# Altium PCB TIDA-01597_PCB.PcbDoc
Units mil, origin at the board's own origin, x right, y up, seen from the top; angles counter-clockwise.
Board outline 1013 x 1011.96 mil, 2 copper layers (Top Layer, Bottom Layer), stack 62 mil thick; 20 components, 17 nets, 61 pads, 15 vias.
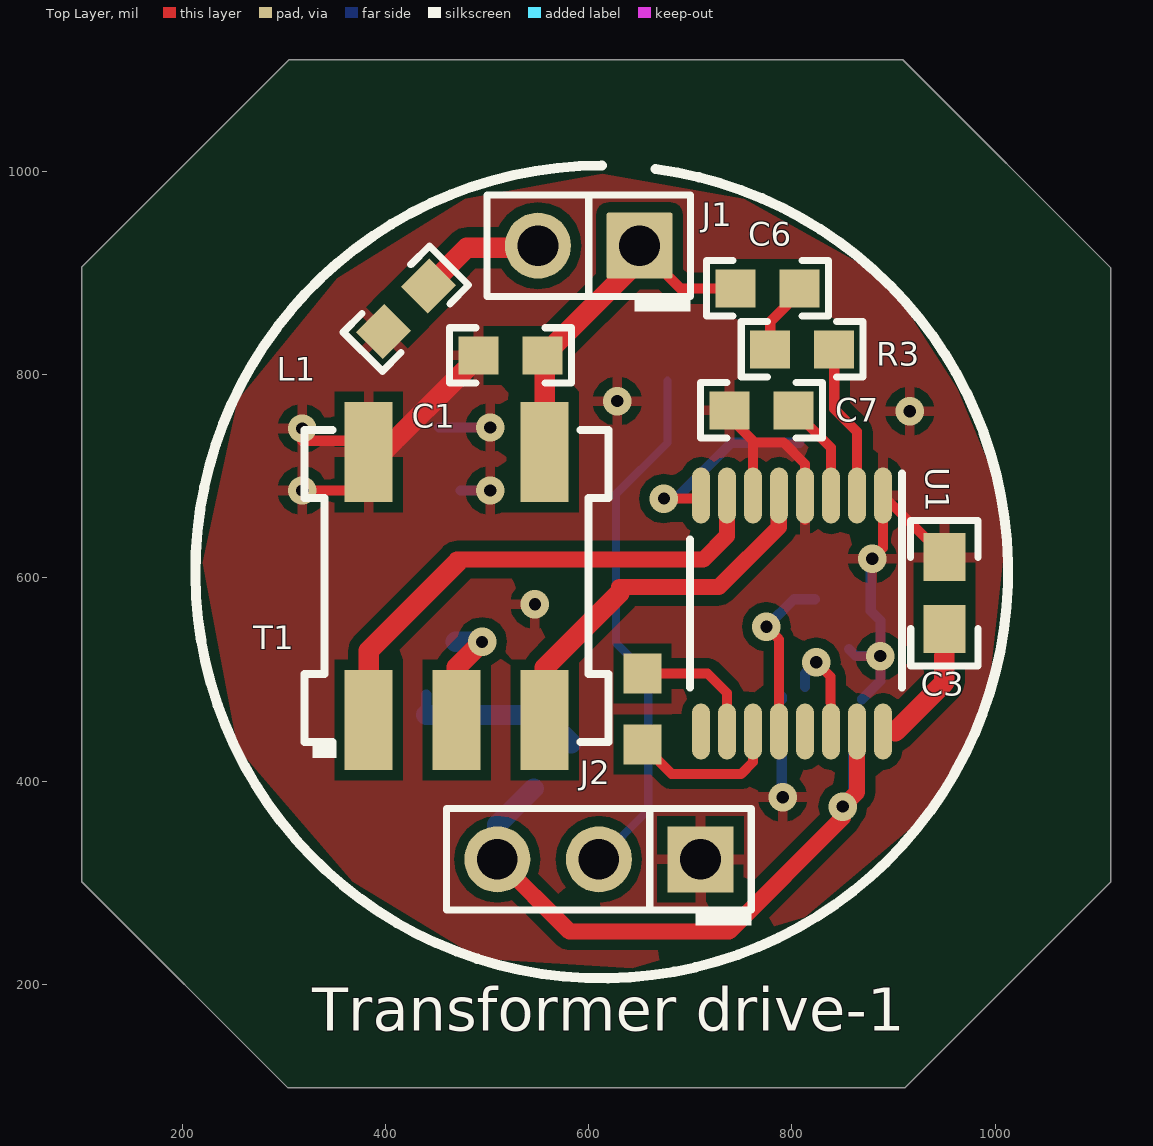
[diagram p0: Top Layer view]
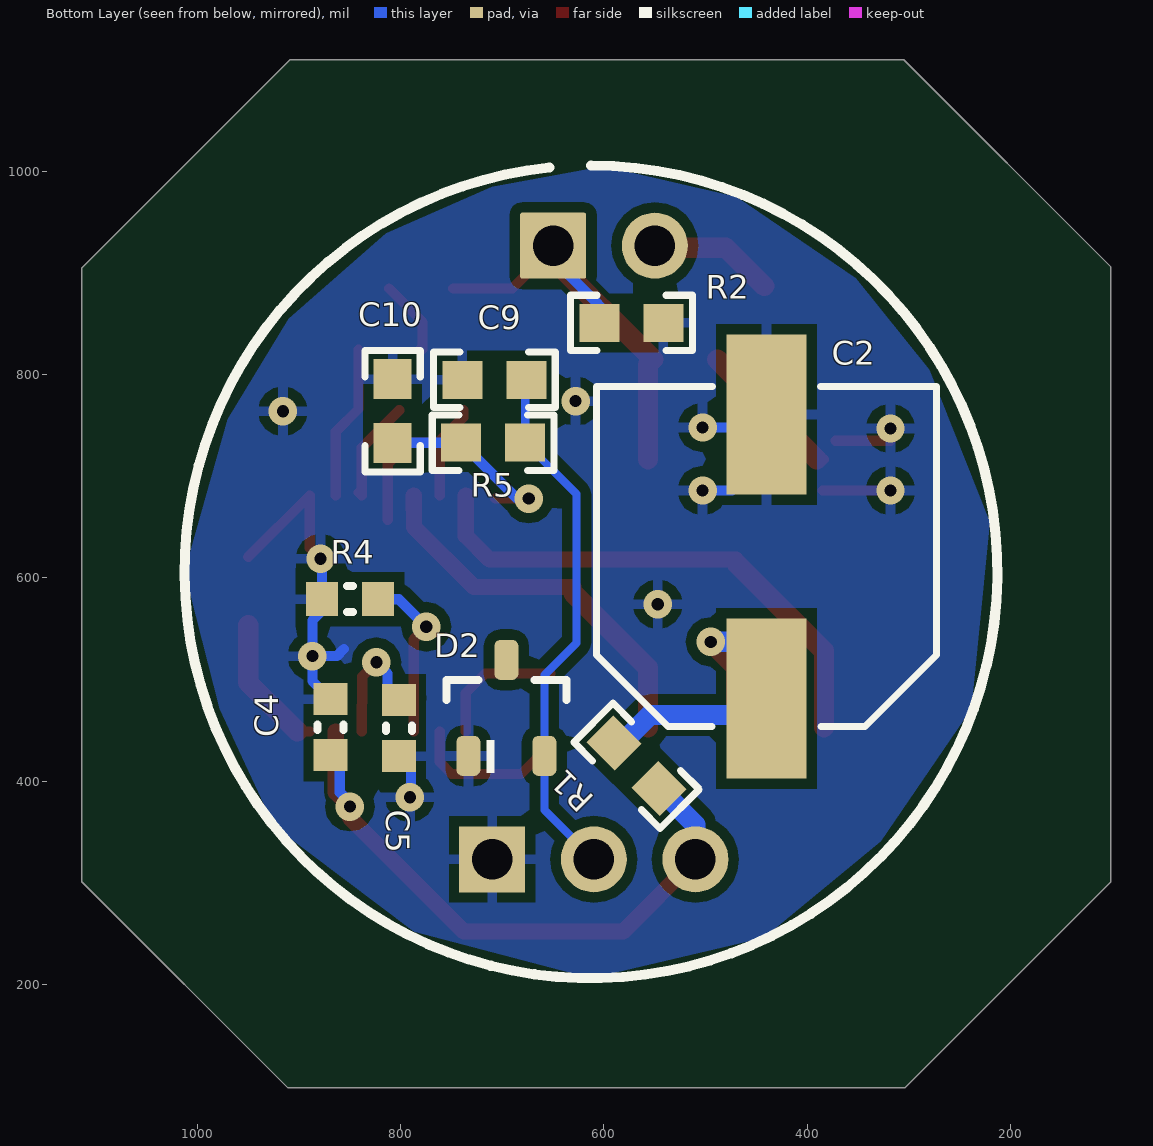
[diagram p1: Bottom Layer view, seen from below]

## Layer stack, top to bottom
Top Solder: solder mask 0.4, Solder Resist, Dk 3.5
Top Layer: signal copper 1.4
Dielectric1: core 59.2, FR-4, Dk 4.8
Bottom Layer: signal copper 1.4
Bottom Solder: solder mask 0.4, Solder Resist, Dk 3.5

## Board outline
304.95,1109.95 909.05,1109.95 1114,905 1114,301 911,98 304,98 101,301 101,906

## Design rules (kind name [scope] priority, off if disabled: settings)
AcuteAngle [All] p1: minimum=4.50000000000000E+0001 checktracksonly=FALSE
AssemblyTestPointUsage [All] p1: valid=2
BoardOutlineClearance BoardOutlineClearance_MountingHoles [OnCopper and InComponentClass('Mounting Holes')] p1: gap=40 ignorepadtopadclearanceinfootprint=FALSE
BoardOutlineClearance BoardOutlineClearance_Poly [OnCopper and IsPoly] p2: gap=25 ignorepadtopadclearanceinfootprint=FALSE
BoardOutlineClearance [OnCopper and Not InComponentClass('Logo') and not InComponentClass('FiducialMark') and not InRegion(1000,500,4000,800) and not InPoly] p3: gap=75 ignorepadtopadclearanceinfootprint=FALSE
Clearance Clearance_Keepouts [((IsTrack Or IsArc) And Not InPoly) And IsFree and IsKeepOut vs ((IsTrack Or IsArc) And Not InPoly) And IsFree and IsKeepOut] p1: gap=0 ignorepadtopadclearanceinfootprint=FALSE
Clearance Clearance_Poly [InPolygon] p2: gap=10 ignorepadtopadclearanceinfootprint=FALSE except(0: Arc-Hole Track-Hole SMDPad-Hole THPad-Hole Via-Hole Fill-Hole Poly-Hole Region-Hole Text-Hole)
Clearance [All] p3: gap=7.87 ignorepadtopadclearanceinfootprint=FALSE except(0: Arc-Hole Track-Hole SMDPad-Hole THPad-Hole Via-Hole Fill-Hole Poly-Hole Region-Hole Text-Hole)
ComponentClearance ComponentClearance_MountingHoles_FiducialMarks [InComponentClass('Mounting Holes') vs InComponentClass('FiducialMark')] p1: gap=50 collisioncheckmode=3 verticalgap=10 showdistances=FALSE
ComponentClearance ComponentClearance_Shunt [InComponentClass('Header') vs InComponentClass('Shunt')] p2: gap=0 collisioncheckmode=3 verticalgap=0 showdistances=FALSE
ComponentClearance ComponentClearance_Logo [InComponentClass('Logo')] p3: gap=50 collisioncheckmode=3 verticalgap=10 showdistances=FALSE
ComponentClearance ComponentClearance_ScrewToNut [(HasFootprint('NY PMS 440 0025 PH')) vs (HasFootprint('Keystone_1902C'))] p4: gap=5 collisioncheckmode=3 verticalgap=10 showdistances=FALSE
ComponentClearance ComponentClearance_MountingHoles [InComponentClass('Mounting Holes')] p5: gap=250 collisioncheckmode=3 verticalgap=100000 showdistances=FALSE
ComponentClearance ComponentClearance_SmallPassives [HasFootprint('0201*') or HasFootprint('0402*') or HasFootprint('0508') or HasFootprint('0603*') or HasFootprint('0612') or HasFootprint('0805*') or HasFootprint('0815*') or HasFootprint('0830*') or HasFootprint('1206*') or HasFootprint('1210*') or HasFootprint('1808*') or HasFootprint('1812*') or HasFootprint('1825*') or HasFootprint('2010*') or HasFootprint('2220*') or HasFootprint('2225*') or HasFootprint('2512*') or HasFootprint('2728*') or HasFootprint('3518*') vs HasFootprint('0201*') or HasFootprint('0402*') or HasFootprint('0508') or HasFootprint('0603*') or HasFootprint('0612') or HasFootprint('0805*') or HasFootprint('0815*') or HasFootprint('0830*') or HasFootprint('1206*') or HasFootprint('1210*') or HasFootprint('1808*') or HasFootprint('1812*') or HasFootprint('1825*') or HasFootprint('2010*') or HasFootprint('2220*') or HasFootprint('2225*') or HasFootprint('2512*') or HasFootprint('2728*') or HasFootprint('3518*')] p6: gap=6 collisioncheckmode=3 verticalgap=10 showdistances=FALSE
ComponentClearance ComponentClearance_THtoSMT [IsThruComponent vs IsSMTComponent] p7: gap=35 collisioncheckmode=3 verticalgap=30 showdistances=FALSE
ComponentClearance ComponentClearance_THtoTH [IsThruComponent vs IsThruComponent] p8: gap=30 collisioncheckmode=3 verticalgap=30 showdistances=FALSE
ComponentClearance [All] p9: gap=30 collisioncheckmode=3 verticalgap=10 showdistances=FALSE
DiffPairsRouting [All] p1: maxlimit=100 minlimit=10 mostfreqgap=10 toplayer_minwidth=15 toplayer_maxwidth=15 toplayer_prefwidth=15 bottomlayer_minwidth=15 bottomlayer_maxwidth=15 bottomlayer_prefwidth=15 maxuncoupledlength=1000
FabricationTestPointUsage TestPointUsage [All] p1: valid=2 allowmultiple=FALSE
FabricationTestpoint Testpoint [All] p1: side=3 testpointundercomponent=TRUE minsize=40 maxsize=100 preferedsize=60 minholesize=0 maxholesize=40 preferedholesize=32 testpointgrid=1 allowsidetop=TRUE allowsidebottom=TRUE usegrid=TRUE gridtolerance=0.01
FanoutControl Fanout_LCC [IsLCC] p1: bgadir=Out bgaviamode=Centered fanoutstyle=Auto fanoutdirection=Alternating viagrid=1 // Fanout_LCC (Default Rule)
FanoutControl Fanout_BGA [IsBGA] p2: bgadir=Out bgaviamode=Centered fanoutstyle=Auto fanoutdirection=Alternating viagrid=1 // Fanout_BGA (Default Rule)
FanoutControl Fanout_Default [All] p4: bgadir=Out bgaviamode=Centered fanoutstyle=Auto fanoutdirection=Alternating viagrid=1 // Fanout_Default (Default Rule)
FanoutControl Fanout_Small [(CompPinCount < 5)] p5: bgadir=Out bgaviamode=Centered fanoutstyle=Auto fanoutdirection=OutThenIn viagrid=1 // Fanout_Small (Default Rule)
HoleSize [All] p1: absolutevalues=TRUE maxlimit=251 minlimit=7.87 maxpercent=80.000 minpercent=20.000
MinimumAnnularRing MinimumAnnularRing_ThermalPadVias [IsVia and InAnyComponent] p1: minimumring=5.91
MinimumAnnularRing [All] p2: minimumring=8
MinimumSolderMaskSliver MinimumSolderMaskSliver_Logo [InComponentClass('Logo') vs InComponentClass('Logo')] p1: minsoldermaskwidth=0.7
MinimumSolderMaskSliver [All] p2: minsoldermaskwidth=3.94
PlaneConnect [All] p1: planeconnectstyle=Relief reliefexpansion=10 reliefentries=4 reliefconductorwidth=10 reliefairgap=10
PolygonConnect [All] p1: connectstyle=Relief reliefconductorwidth=10 reliefentries=4 polygonreliefangle="90 Angle" airgapwidth=10
RoutingVias ThermalPadVias [IsVia and InAnyComponent] p1: holewidth=7.87 width=19.68 viastyle="Through Hole" minholewidth=7.87 minwidth=19.68 maxholewidth=12.99 maxwidth=23.62
RoutingVias [All] p2 off: holewidth=16 width=34 viastyle="Through Hole" minholewidth=7.87 minwidth=26 maxholewidth=40 maxwidth=65
SilkToBoardRegionClearance [Not ((IsComment or IsDesignator) And (Hide <> 'False')) and not InRegion(1000,500,4000,800)] p1:
SilkToSilkClearance SilkToSilkClearance_Pb-FreeLogo [(HasFootprint('Pb-Free_Overlay_Medium') OR HasFootprint('Pb-Free_Overlay_Small')) vs (HasFootprint('Pb-Free_Overlay_Medium') OR HasFootprint('Pb-Free_Overlay_Small'))] p1: silktosilkclearance=0
SilkToSilkClearance [All] p2: silktosilkclearance=4
SilkToSolderMaskClearance SilkToComponentPadClearance [(IsPad or IsFill or IsRegion) and InAnycomponent] p1 off: minsilkscreentomaskgap=5 clearancetoexposedcopper=TRUE
SilkToSolderMaskClearance "Silk to Solder Mask Opening" [All] p2 off: minsilkscreentomaskgap=4 clearancetoexposedcopper=FALSE
SolderMaskExpansion [All] p1: expansion=1.97
Width [All] p1: maxlimit=100 minlimit=6 preferedwidth=10 checkconnectedcopper=TRUE
15 further rules are at their usual default settings.

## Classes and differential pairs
component class Header: J1 J2 J9 J10

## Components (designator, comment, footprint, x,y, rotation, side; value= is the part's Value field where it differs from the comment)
C1 "GRM188R72A152KA01D" 0603 523,819 r180 top value=1500pF
C2 "EEE-FK1V101P" SM_RADIAL_F 440,621 r90 bottom value=100uF
C3 "C1608X7R1E104K080AA" 0603M 950.08,584.94 r90 top value=0.1uF
C4 "C1608X7R1E104K080AA" 0603L 869,453 r90 bottom value=0.1uF
C5 "C1608X7R1E104K080AA" 0603L 802,452 r270 bottom value=0.1uF
C6 "GRM1885C2A391JA01D" 0603 776,885 r180 top value=390pF
C7 "06035C333JAT2A" 0603 770.08,764.94 r180 top value=0.033uF
C9 "GRM1885C1H181JA01D" 0603 708,795 r0 bottom value=180pF
C10 "GRM1885C1H181JA01D" 0603 808,764 r90 bottom value=180pF
D2 "MMBZ27VCL-7-F" SOT-23 696,472 r90 bottom value=27V
J1 "TSW-102-07-G-S" TSW-102-07-G-S 600,927 r180 top
J2 "TSW-103-07-G-S" TSW-103-07-G-S 610,323 r180 top
L1 "74279264" 0603 420.08,864.94 r45 top value="300 ohm"
R1 "CRCW0603100RJNEA" 0603 568,415 r225 bottom value=100
R2 "RC0603JR-072K7L" 0603 573,851 r0 bottom value=2.7k
R3 "CRCW0603100RJNEA" 0603 810.08,824.94 r0 top value=100
R4 "RC0603JR-0710KL" 0603L 850,579 r180 bottom value=10k
R5 "CRCW0603100RFKEA" 0603 709,733 r0 bottom value=100
T1 "B78416A2232A003" TDK_B78416A2232A003 470,592 r90 top value=3mH
U1 "PGA460TPWRQ1" PW0016A_N 800.08,564.94 r270 top

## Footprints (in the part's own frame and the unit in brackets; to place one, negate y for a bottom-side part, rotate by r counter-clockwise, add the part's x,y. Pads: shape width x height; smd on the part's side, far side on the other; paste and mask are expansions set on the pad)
0603 [mm] "0603 from SM-752 data"
  rect 1x0.95 smd: 1(-0.8,0) 2(0.8,0)
  silkscreen extent -1.52,-0.69 1.52,0.69, body extent -0.87,-0.47 0.87,0.47, height 1
0603L [mm] "0603 from SM-752 data"
  rect 0.8x0.85 smd: 1(-0.7,0) 2(0.7,0)
  silkscreen extent -0.07,-0.33 0.07,0.33, body extent -0.87,-0.47 0.87,0.47, height 1
0603M [mm] "0603 from SM-752 data"
  rect 1.2x1.05 smd: 1(-0.9,0) 2(0.9,0)
  silkscreen extent -1.82,-0.84 1.82,0.84, body extent -0.87,-0.47 0.87,0.47, height 1
PW0016A_N [mm] "TSOP, 16-Leads, Body 5x4.4mm, Pitch 0.65mm, IPC Medium Density"
  oval 1.4x0.45 smd: 1(-2.95,2.275) 2(-2.95,1.625) 3(-2.95,0.975) 4(-2.95,0.325) 5(-2.95,-0.325) 6(-2.95,-0.975) 7(-2.95,-1.625) 8(-2.95,-2.275) 9(2.95,-2.275) 10(2.95,-1.625) 11(2.95,-0.975) 12(2.95,-0.325) 13(2.95,0.325) 14(2.95,0.975) 15(2.95,1.625) 16(2.95,2.275)
  silkscreen extent -3.5,-2.55 1.85,2.75, body extent -3.21,-2.5 3.21,2.5, height 1
SM_RADIAL_F [mm] "8 x 10.2mm:  Panasonic F"
  rect 4x2 smd: 1(-3.55,0) 2(3.55,0)
  silkscreen extent -4.25,-4.25 4.25,4.25, body extent -4.25,-4.25 4.25,4.25, height 10.5
SOT-23 [mm] "SOT23, 3-Leads, Body 2.9x1.3mm, Pitch 0.95mm, Lead Span 2.5mm, IPC Medium Density"
  rrect50% 1x0.6 smd: 1(-1.2,0.95) 2(-1.2,-0.95) 3(1.2,0)
  silkscreen extent -1.62,-1.5 0.7,1.5, body extent -1.16,-1.45 1.21,1.45, height 1
TDK_B78416A2232A003 [mm] "SMT, 5-Leads, Body 8.8x7.6mm"
  rect 2.5x1.2 smd: 1(-3.35,2.2) 2(-3.35,0) 3(-3.35,-2.2) 4(3.35,-2.2) 6(3.35,2.2)
  silkscreen extent -4.3,-3.8 3.9,3.8, body extent -4.5,-3.8 4.5,3.8, height 7.1
TSW-102-07-G-S [mm] "Samtec 100mil, 1x2, 230 mil above insulator"
  rrect6% 1.65x1.65 hole 1.016: 1(-1.27,0)
  round 1.65 hole 1.016: 2(1.27,0)
  silkscreen extent -2.54,-1.27 2.54,1.65, body extent -2.54,-1.27 2.54,1.27, height 8.38
TSW-103-07-G-S [mm] "Samtec 100mil, 1x3, 230 mil above insulator"
  rect 1.65x1.65 hole 1.016: 1(-2.54,0)
  round 1.65 hole 1.016: 2(0,0) 3(2.54,0)
  silkscreen extent -3.81,-1.27 3.81,1.65, body extent -3.81,-1.27 3.81,1.27, height 8.38

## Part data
C1: "CAP, CERM, 1500 pF, 100 V, +/- 10%, X7R, 0603", Cap_Case=0603, Manufacturer=MuRata, Supplier Part Number 1=490-1475-1-ND, TempCo=X7R, Tolerance_%=10, Value1=Unknown, Value2=100V, ValueDisplayed=1500pF
C2: "CAP, AL, 100 µF, 35 V, +/- 20%, 0.16 ohm, AEC-Q200 Grade 2, SMD", Cap_Case=F, Manufacturer=Panasonic, Supplier Part Number 1=PCE3835CT-ND, Tolerance_%=20, Value1="0.16 ohm", Value2=35V, ValueDisplayed=100µF
C3 C4 C5: "CAP, CERM, 0.1 µF, 25 V, +/- 10%, X7R, 0603", Cap_Case=0603, Manufacturer=TDK, Supplier Part Number 1=445-1316-1-ND, TempCo=X7R, Tolerance_%=10, Value1=Unknown, Value2=25V, ValueDisplayed=0.1µF
C6: "CAP, CERM, 390 pF, 100 V, +/- 5%, C0G/NP0, 0603", Cap_Case=0603, Manufacturer=MuRata, Supplier Part Number 1=490-1365-1-ND, TempCo=C0G/NP0, Tolerance_%=5, Value1=Unknown, Value2=100V, ValueDisplayed=390pF
C7: "CAP, CERM, 0.033 µF, 50 V, +/- 5%, X7R, 0603", Cap_Case=0603, Manufacturer=AVX, Supplier Part Number 1=478-3723-1-ND, TempCo=X7R, Tolerance_%=5, Value1=Unknown, Value2=50V, ValueDisplayed=0.033µF
C9 C10: "CAP, CERM, 180 pF, 50 V,+/- 5%, C0G/NP0, 0603", Cap_Case=0603, Manufacturer=MuRata, Supplier Part Number 1=490-1433-1-ND, TempCo=C0G/NP0, Tolerance_%=5, Value2=50V, ValueDisplayed=180pF
D2: "Diode, TVS, Uni, 27 V, 38 Vc, SOT-23", Manufacturer="Diodes Inc.", Power_W=0.225, Supplier Part Number 1=MMBZ27VCL-FDICT-ND, Value1=0.225W
J1: "Header, 100mil, 2x1, Gold, TH", Color=Black, Current_A=6.3, Manufacturer=Samtec, Supplier Part Number 1=SAM1029-02-ND, Voltage_V=550
J2: "Header, 100mil, 3x1, Gold, TH", Color=Black, Current_A=6.3, Manufacturer=Samtec, Supplier Part Number 1=SAM1029-03-ND, Voltage_V=550
L1: "Ferrite Bead, 300 ohm @ 100 MHz, 0.2 A, 0603", Manufacturer="Wurth Elektronik", Supplier Part Number 1=732-4630-1-ND, Value1="0.35 ohm", Value2=0.2A, ValueDisplayed="300 ohm"
R1 R3: "RES, 100, 5%, 0.1 W, 0603", Manufacturer=Vishay-Dale, Power_W=0.1, Supplier Part Number 1=541-100GCT-ND, TempCo="200 ppm/C", Tolerance_%=5, Value1=5%, Value2=0.1W, Value_Code=100R, ValueDisplayed=100
R2: "RES, 2.7 k, 5%, 0.1 W, 0603", Manufacturer="Yageo America", Power_W=0.1, Supplier Part Number 1=311-2.7KGRCT-ND, TempCo="100 ppm/C", Tolerance_%=5, Value1=5%, Value2=0.1W, Value_Code=2k70, ValueDisplayed=2.7k
R4: "RES, 10 k, 5%, 0.1 W, 0603", Manufacturer="Yageo America", Power_W=0.1, Supplier Part Number 1=311-10KGRCT-ND, TempCo="100 ppm/C", Tolerance_%=5, Value1=5%, Value2=0.1W, Value_Code=10k0, ValueDisplayed=10k
R5: "RES, 100, 1%, 0.1 W, 0603", Manufacturer=Vishay-Dale, Power_W=0.1, Supplier Part Number 1=541-100HCT-ND, TempCo="100 ppm/C", Tolerance_%=1, Value1=1%, Value2=0.1W, Value_Code=100R, ValueDisplayed=100
T1: "Transformer, 3 mH, SMT", Manufacturer=TDK, Supplier Part Number 1=495-6812-1-ND, ValueDisplayed=3mH
U1: "PGA460TPWRQ1, PW0016A (TSSOP-16)", Alternate Manufacturer="Texas Instruments"

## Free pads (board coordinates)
  rect 37.4x39.37 smd: 105(652.78,505.91) 106(652.78,435.91)

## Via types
v1: diameter 28, hole 12, Top Layer to Bottom Layer, 15 vias

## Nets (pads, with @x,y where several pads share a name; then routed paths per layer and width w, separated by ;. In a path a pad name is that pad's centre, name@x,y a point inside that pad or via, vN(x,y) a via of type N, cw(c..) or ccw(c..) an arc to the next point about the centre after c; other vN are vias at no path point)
GND: C1.2 C2.2 C3.2 C4.2 C5.2 C7.2 C9.2 C10.2 D2.1 J2.1 L1.1 R2.1 R4.1 T1.6 U1.1 U1.4 U1.6 | length 926
  Top Layer w10: v1(318,686) T1.6@385,686 ; v1@318,735 T1.6@372.28,735 ; T1.6@383.46,716.83 T1.6@390.47,716.83 ; C7.2 738.58,758.05 761.69,734.94 ; U1.6 761.69,734.94 ; U1.4@812.87,657.14 U1.4 812.87,712.14 791.65,733.37 763.27,733.37 761.69,734.94 ; v1(879,618.86) 889.65,629.51 U1.1 C3.2@950.08,620.65
  Top Layer w20: T1.6@390.47,716.83 C1.2@488.58,814.94
  Bottom Layer w10: C2.2@452.76,748 v1@501,748 ; C2.2@474,686 v1@501,686 ; v1@790,385 C5.2@790,425.44 ; 856,530 863,523 v1(887,523) ; C4.2 887,498.56 v1(887,523) ; v1@877.56,617.42 R4.1 877.56,567.44 887,558 v1(887,523)
  other v1: 791,384 547,574 503,686 318,747 503,748 916,764 628,774
NetC1_1: C1.1 C6.2 J1.1 R2.2 T1.4 | length 473.7
  Top Layer w10: C1.1@551.57,814.94 C1.1@556.69,809.82 ; J1.1@650.08,924.94 690.08,884.94 C6.2@748.58,884.94
  Top Layer w20: C1.1@551.57,814.94 J1.1@654,917 ; T1.4@556.69,716.83 C1.1@556.69,809.82
  Bottom Layer w10: R2.2@590.39,853.64 J1.1@652,916 ; J1.1@651.57,906.44 J1.1@670.08,924.94
NetC2_1: C2.1 R1.1 T1.2 | length 290.6
  Top Layer w20: T1.2 470,512 v1(495,537)
  Bottom Layer w10: C2.1@440.08,465.18 C2.1@440.08,484.94 ; v1@496,538 v1@497,537
  Bottom Layer w20: C2.1@440.08,465.18 555,465 R1.1@582.73,437.27 ; C2.1@469,537 v1(495,537) v1@497,537
NetC3_1: C3.1 U1.16 | length 136.7
  Top Layer w10: U1.16 901.8,448.8
  Top Layer w20: 901.8,449 902,449 950,497 C3.1@950.08,553.44
NetC5_1: C5.1 U1.14 | length 105.4
  Top Layer w10: v1(824,517) 838,503 U1.14
  Bottom Layer w10: C5.1@790,480.56 C5.1@790,483 ; C5.1@813,492.56 813,506 v1(824,517)
NetC6_1: C6.1 R3.1 | length 76.7
  Top Layer w10: R3.1@781.57,824.94 R3.1 778.58,851.95 C6.1@811.57,884.94
NetC7_1: C7.1 U1.3 | length 103.5
  Top Layer w10: C7.1 838.46,728.05 U1.3 U1.3@841.57,684.19
NetC9_1: C9.1 D2.2 J2.2 R5.1 | length 525.1
  Bottom Layer w8: J2.2 658.6,371.6 658.6,489.76 658.6,504.4 627,536 627,682.5 R5.1 C9.1@677.5,794
NetC10_1: C10.1 R5.2 U1.8 | length 189.7
  Top Layer w10: v1(674,678) U1.8@707.43,678
  Bottom Layer w10: v1(674,678) 685.5,678 R5.2 C10.1@807.5,733
NetJ1_2: J1.2 L1.2 | length 123.4
  Top Layer w20: L1.2 480.08,924.94 J1.2@550.08,924.94
NetR3_2: R3.2 U1.2 | length 153.2
  Top Layer w10: R3.2 841.57,766.27 864.06,743.79 U1.2
NetR4_2: R4.2 U1.12 | length 167
  Top Layer w10: v1(774.86,551.86) 787.28,539.44 U1.12
  Bottom Layer w10: v1(774.86,551.86) 802,579 R4.2
NetT1_1: T1.1 U1.7 | length 513.2
  Top Layer w16: 470,618 712.73,618 736.02,641.29 U1.7
  Top Layer w20: T1.1@383.46,453.05 383.46,528.33 470.08,614.94
NetT1_3: T1.3 U1.5 | length 374.8
  Top Layer w16: 630,591 728,591 787,650 U1.5
  Top Layer w20: T1.3@556.69,453.05 556.69,511.55 630.08,584.94
RXD: pad.106 U1.11 | length 155.8
  Top Layer w10: pad.106 681.68,407 750,407 761.69,418.69 U1.11
TXD: pad.105 U1.10 | length 129.2
  Top Layer w10: pad.105 716.92,505.91 736.1,486.73 U1.10
VPWR: C4.1 J2.3 R1.2 U1.15 | length 645.6
  Top Layer w16: J2.3 581,252 738,252 850.08,364.08 v1(850.08,374.94) 864.06,388.92 U1.15
  Bottom Layer w10: v1(850.08,374.94) 850.08,379.08 860,389 C4.1@860,425.44
  Bottom Layer w20: J2.3 510,357 R1.2
pads on no net: D2.3 U1.9 U1.13

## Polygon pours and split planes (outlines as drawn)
GND on Top Layer "TOP_LAYER_GND_P010" (solid, remove dead copper, pour order 10): 613.27,997.91 752.78,972.91 892.78,894.94 962.78,785.91 1012.78,665.91 993.27,486.4 942.78,375.91 812.78,265.91 642.78,215.91 492.78,224.94 367.78,300.91 254.5,432.4 220.08,614.94 254.5,774.94 352.43,894.94 478.27,972.91
GND on Bottom Layer "BOTTOM_LAYER_GND_P012" (solid, remove dead copper, pour order 12): 710.08,984.94 814.32,939.18 910.08,854.94 970.08,755.91 1012.78,605.91 978.3,471.43 924.34,355.35 786.91,251.77 612.78,205.91 442.78,245.91 327.78,340.91 238.3,471.43 220.08,654.94 280.08,804.94 352.43,894.94 469.79,974.94 600.08,1004.94

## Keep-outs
Keep-Out Layer:
  text ".Layer_Name" at 577,-858.49 h60

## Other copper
Bottom Layer:
  text ".Layer_Name" at 577,-858.49 h60

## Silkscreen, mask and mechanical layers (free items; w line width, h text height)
Top Overlay:
  lines w10: 612.78,1005.91 ccw(c612.78,605.91) 665.6,1002.4
  text "Transformer drive-1" at 327.62,140 h72.83
Bottom Overlay:
  lines w10: 612.78,1005.91 ccw(c612.78,605.91) 653.94,1003.78
  text ".Layer_Name" at 577,-858.49 h60
Bottom Paste:
  text ".Layer_Name" at 577,-858.49 h60
Bottom Solder:
  text ".Layer_Name" at 577,-858.49 h60
Drill Guide:
  text ".Layer_Name" at 577,-858.49 h60
M1 Board Outline:
  lines w10: 607,1103.31 907,1103.31 1107,903.31 1107,570 ; 617.62,1103.31 307,1103.31 107,903.31 107,603.31 107,303.31 307,103.31 607,103.31 907,103.31 ; 897,103.31 907,103.31 ; 1107,603.31 1107,303.31 907,103.31
  text ".Layer_Name" at 577,-858.49 h60
M2 Board Dimensions:
  rectangle: 125,-400 500,-275
  rectangle: 0,-275 125,-150
  lines w7: 0,-275 1000,-275 ; 125,-400 125,-150 ; 250,-400 250,-150 ; 500,-400 500,-150 ; 750,-400 750,-150 ; 0,-400 0,-150 1000,-150 1000,-400 0,-400
  text ".Layer_Name" at 577,-858.49 h60
M3 3D STEP Top:
  text ".Layer_Name" at 577,-858.49 h60
M4 3D STEP Bottom:
  text ".Layer_Name" at 577,-858.49 h60
M5 Assembly Top:
  lines w10: -292,-930.17 6308,-930.17 ; -292,-726.83 6310,-726.83 ; -292,-523.5 -292,-1133.5 3713,-1133.5 6310,-1133.5 6310,-523.5 -291.5,-523.5 -291.5,-1133.5 1284,-1133.5 ; 2173,-1133.5 2173,-523.5 ; 3440,-726.83 3440,-523.5 ; 4280,-726.83 4280,-523.5 ; 4902,-1140 4902,-937.17
  text "COMPONENTS MARKED 'DNP' SHOULD NOT BE POPULATED." at 1153.5,-318.5 h60
  text "ASSEMBLY VARIANT:" at 1153,-434 h60
  text ".VariantName" at 2189,-434 h60
  text "PCB VIEWED FROM TOP SIDE" at -228.5,-655.67 h60
  text "BOARD #:" at 2248,-655.67 h60
  text ".PRJ_Number" at 2793.5,-655.67 h60
  text "REV:" at 3638,-655.67 h60
  text ".PCB_Rev" at 3929.5,-655.67 h60
  text "SVN REV:" at 4476,-655.67 h60
  text ".VersionControl_RevNumber" at 4982,-655.67 h60
  text "TID #:" at 2248,-859 h60
  text ".TID" at 2793.5,-859 h60
  text "PLOT NAME =" at -228.5,-1064.34 h60
  text ".plot_File_Name" at 577,-1064.34 h60
  text "GENERATED    :" at 2250,-1064.34 h60
  text ".Print_Date" at 3119.5,-1064.34 h60
  text ".Print_Time" at 3848.5,-1064.34 h60
  text "TEXAS INSTRUMENTS" at 5113,-1064.34 h60
M6 Assembly Bottom:
  lines w10: -292.5,-727.33 6309.5,-727.33 ; -290.5,-930.67 6309.5,-930.67 ; 1115.5,-1140.5 1115.5,-937.67 ; 1737.5,-727.33 1737.5,-524 ; 2577.5,-727.33 2577.5,-524 ; 3844.5,-1134 3844.5,-524 ; 4733.5,-1134 6309,-1134 6309,-524 -292.5,-524 -292.5,-1134 2304.5,-1134 6309.5,-1134 6309.5,-524
  text "COMPONENTS MARKED 'DNP' SHOULD NOT BE POPULATED." at 6102,-318 h60
  text ".VariantName" at 5058,-434 h60
  text "ASSEMBLY VARIANT:" at 6097,-434 h60
  text ".VersionControl_RevNumber" at 1035.5,-656.17 h60
  text "SVN REV:" at 1541.5,-656.17 h60
  text ".PCB_Rev" at 2088,-656.17 h60
  text "REV:" at 2379.5,-656.17 h60
  text ".PRJ_Number" at 3224,-656.17 h60
  text "BOARD #:" at 3769.5,-656.17 h60
  text "PCB VIEWED FROM BOTTOM SIDE" at 6246,-656.17 h60
  text ".TID" at 3224,-859.5 h60
  text "TID #:" at 3769.5,-859.5 h60
  text "TEXAS INSTRUMENTS" at 904.5,-1064.84 h60
  text ".Print_Time" at 2169,-1064.84 h60
  text ".Print_Date" at 2898,-1064.84 h60
  text "GENERATED    :" at 3767.5,-1064.84 h60
  text ".plot_File_Name" at 5440.5,-1064.84 h60
  text "PLOT NAME =" at 6246,-1064.84 h60
M9 Title Sheet:
  drawing of 57 lines, arcs and shapes, not listed
  text "1" at 739.84,8036.5 h70
  text "2" at 3235.5,8036.5 h70
  text "3" at 5724.84,8036.5 h70
  text "4" at 8231.51,8036.5 h70
  text "5" at 10730.5,8036.5 h70
  text "6" at 13235.5,8036.5 h70
  text "A" at -416.5,6893.5 h70
  text "A" at 14383.5,6893.5 h70
  text "B" at -416.5,4513.5 h70
  text "B" at 14383.5,4513.5 h70
  text "C" at -416.5,2138.5 h70
  text "C" at 14383.5,2138.5 h70
  text "PROJECT TITLE:" at 11343.5,277.5 h45
  text ".PRJ_Title" at 11393.5,144.17 h70
  text "DESIGNED FOR:" at 11343.5,-23.5 h45
  text ".PRJ_Customer" at 11393.5,-163.5 h70
  text "D" at -416.5,-231.5 h70
  text "D" at 14383.5,-231.5 h70
  text "FILE NAME:" at 11343.5,-323.5 h45
  text ".PCB_File_Name_No_Path" at 11393.5,-443.5 h70
  text "Texas Instruments (TI) and/or its licensors do not warrant the accuracy or completeness of this specification" at 6374,-605.34 h45
  text "ENGINEER:" at 11343.5,-613.5 h45
  text "LAYOUT BY:" at 12848.5,-613.5 h45
  text "or any information contained therein. TI and/or its licensors do not warrant that this design will meet" at 6329.01,-718 h45
  text ".PRJ_Engineer" at 11393.5,-768.49 h70
  text ".PCB_Layout" at 12899,-768.49 h70
  text "the specifications, will be suitable for your application or fit for any particular purpose, or will operate in" at 6329.01,-830.67 h45
  text ".Layer_Name" at 577,-858.49 h60
  text "ALTIUM DESIGNER VERSION:" at 12848.5,-923.5 h45
  text "an implementation. TI and/or its licensors do not warrant that the design is production worthy. You should" at 6329.01,-943.33 h45
  text "completely validate and test your design implementation to confirm the system functionality for your application." at 6374,-1056 h45
  text ".print_Scale" at 11393.5,-1056.83 h70
  text ".Application_BuildNumber" at 12899,-1056.83 h70
  text "1" at 739.84,-1263.5 h70
  text "2" at 3235.5,-1263.5 h70
  text "3" at 5724.84,-1263.5 h70
  text "4" at 8231.51,-1263.5 h70
  text "5" at 10730.5,-1263.5 h70
  text "6" at 13235.5,-1263.5 h70
M10 Fab Notes:
  drawing of 173 lines, arcs and shapes, not listed
  text "DESIGN INFORMATION" at 12378.02,6201 h60
  text "MIN. TRACK WIDTH:" at 11733.46,6021 h60
  text "8" at 12829.7,6021 h60
  text "MIL" at 12984.46,6021 h60
  text "MIN. CLEARANCE:" at 11733.46,5889 h60
  text "0.2" at 12769.7,5889 h60
  text "mm" at 12984.46,5889 h60
  text "MIN. VIA PAD SIZE:" at 11733.46,5757 h60
  text "24" at 12799.71,5757 h60
  text "MIL" at 12984.46,5757 h60
  text "0.05mm (2MIL)" at 12428.46,5615.29 h60
  text "MINIMUM ANNULAR RING" at 11404.23,5611 h60
  text "EXTERNAL" at 13136.46,5611 h60
  text "PER" at 11604.23,5493 h60
  text "IPC-D-275 CLASS 2 LEVEL C" at 11824.23,5493 h60
  text "MIL, HOLES" at 13312.46,5380.71 h60
  text "+/-" at 12920,5380 h60
  text "+/-" at 13774,5380 h60
  text "REGISTRATION TOLERANCES:" at 11404.23,5375 h60
  text "METAL" at 12604,5375 h60
  text "5" at 13180.2,5375 h60
  text "3" at 14013.2,5375 h60
  text "MIL" at 14129.46,5375 h60
  text "+/-" at 13774,5262 h60
  text "HOLE SIZE TOLERANCE (UNLESS OTHERWISE SPECIFIED):" at 11404.23,5257 h60
  text "3" at 14013.2,5257 h60
  text "MIL" at 14129.46,5257 h60
  text "MATERIAL:" at 11329.46,5047.54 h60
  text "FR-4 High Tg" at 12315.9,4907.21 h60
  text "FR-408" at 11750.46,4898.64 h60
  text "OTHER" at 13238.46,4898.64 h60
  text "X" at 12161,4895 h60
  text "62 MIL (1.6mm) +/-10%" at 12070.56,4735.92 h60
  text "THICKNESS:" at 11404.23,4731.64 h60
  text "X" at 11942.4,4731.64 h60
  text "OTHER" at 13355.46,4731.64 h60
  text "TOLERANCE:" at 11404.23,4573.64 h60
  text "X" at 12243.53,4573.64 h60
  text "ANSI IPC-6012 TYPE 3 CLASS 2" at 12430.48,4573.64 h60
  text "OTHER +/-" at 12430.46,4417.64 h60
  text "BOW & TWIST:" at 11404.23,4260.64 h60
  text "X" at 12243.53,4260.64 h60
  text "ANSI IPC-6012 TYPE 3 CLASS 2" at 12430.48,4260.64 h60
  text "OTHER +/-" at 12430.46,4102.13 h60
  text "DRILLING:" at 11329.46,3963.64 h60
  text "REFERENCE:" at 11404.23,3846.64 h60
  text "X" at 12052.46,3846.64 h60
  text "AS SHOWN" at 12239.46,3846.64 h60
  text "X" at 12953.46,3846.64 h60
  text "NC_DRILL FILES" at 13090.46,3846.64 h60
  text "PTH COPPER THICKNESS:" at 11404.23,3688.64 h60
  text "X" at 12534.46,3688.64 h60
  text "20-30 um" at 12671.46,3688.64 h60
  text "OTHER" at 13388.46,3688.64 h60
  text "BOARD FINISH:" at 11329.46,3529.64 h60
  text "SILKSCREEN:" at 11484.68,3411.64 h60
  text "X" at 12433.46,3411.64 h60
  text "TOP" at 12559.46,3411.64 h60
  text "X" at 12943.46,3411.64 h60
  text "BOTTOM" at 13070.46,3411.64 h60
  text "BLACK" at 13646.46,3261.44 h60
  text "SILKSCREEN COLOR:" at 11484.68,3244.64 h60
  text "X" at 12432.42,3244.64 h60
  text "WHITE" at 12559.46,3244.64 h60
  text "OTHER" at 13070.46,3244.64 h60
  text "GREEN" at 12690.46,3085.44 h60
  text "OTHER" at 13308.46,3085.44 h60
  text "X" at 13156,3083 h60
  text "SOLDER RESIST COLOR:" at 11484.68,3074.64 h60
  text "X" at 12563.42,2915.44 h60
  text "MATTE" at 12690.46,2915.44 h60
  text "SEMI-GLOSS" at 13308,2914.8 h60
  text "IMMERSION GOLD (ENIG)" at 12390.46,2726.92 h60
  text "ENEPIG" at 13728,2723.64 h60
  text "SURFACE FINISH:" at 11329.46,2722.64 h60
  text "X" at 12203.51,2722.64 h60
  text "IMM. TIN/SILVER OR EQUIV" at 11659,2565.64 h60
  text "OTHER" at 13090.46,2565.64 h60
  text "ARRAY/PANEL:" at 11329.46,2386.64 h60
  text "CUT AND TRIM PER M1 BOARD OUTLINE" at 12390.46,2382.35 h60
  text "N.C. ROUTE" at 12390.46,2230.64 h60
  text "X" at 13069.46,2230.64 h60
  text "V. SCORE" at 13256.46,2230.64 h60
  text "CERTIFICATION:" at 11329.46,2093.64 h60
  text "MATERIALS AND WORKMANSHIP FOR ALL PCBS" at 12054.46,2093.64 h60
  text "TO MEET OR EXCEED THE REQUIREMENTS OF:" at 12054.46,1995.64 h60
  text "X" at 11680.96,1859.13 h60
  text "ANSI IPC-A-600F CLASS ->" at 11819.96,1859.13 h60
  text "X" at 13459.02,1859.13 h60
  text "2" at 13577.96,1859.14 h60
  text "1" at 13262.96,1857.64 h60
  text "3" at 13931.96,1857.64 h60
  text "X" at 12495.02,1699.64 h60
  text "RoHS" at 12631.96,1699.64 h60
  text "OTHER" at 13276.36,1699.64 h60
  text "PER ORDER" at 13673.42,1699.64 h60
  text "ALL BOARDS MUST MEET OR EXCEED UL94-V0 REQUIREMENTS." at 11357,1534 h60
  text "PCB MUST BEAR THE UL94V-0 UL REGISTERED MATERIAL ID NUMBER" at 11357,1414 h60
  text "ADDITIONAL REQUIREMENTS:" at 11329.46,1240.64 h60
  text "MICROSECTION:" at 11404.23,1125.64 h60
  text "YES" at 12309.96,1125.64 h60
  text "REQUIRED" at 13171.46,969.49 h60
  text "BARE BOARD ELEC. TEST:" at 11404.23,966.64 h60
  text "NONE" at 12709.96,966.64 h60
  text "X" at 13044.46,966.64 h60
  text "PER ORDER" at 13763.46,966.64 h60
  text ".Layer_Name" at 577,-858.49 h60
M11 Gerber Information:
  lines w10: -292,-930.17 6308,-930.17 ; -292,-726.83 6310,-726.83 ; -292,-523.5 -292,-1133.5 3713,-1133.5 6310,-1133.5 6310,-523.5 -291.5,-523.5 -291.5,-1133.5 1284,-1133.5 ; 2173,-1133.5 2173,-523.5 ; 3440,-726.83 3440,-523.5 ; 4280,-726.83 4280,-523.5 ; 4902,-1140 4902,-937.17
  text "ALL ARTWORK VIEWED FROM TOP SIDE" at -228.5,-655.67 h60
  text "BOARD #:" at 2248,-655.67 h60
  text ".PRJ_Number" at 2793.5,-655.67 h60
  text "REV:" at 3638,-655.67 h60
  text ".PCB_Rev" at 3929.5,-655.67 h60
  text "SVN REV:" at 4476,-655.67 h60
  text ".VersionControl_RevNumber" at 4982,-655.67 h60
  text "LAYER NAME =" at -228.5,-858.49 h60
  text "TID #:" at 2248,-859 h60
  text ".TID" at 2793.5,-859 h60
  text "PLOT NAME =" at -228.5,-1064.34 h60
  text ".plot_File_Name" at 577,-1064.34 h60
  text "GENERATED    :" at 2250,-1064.34 h60
  text ".Print_Date" at 3119.5,-1064.34 h60
  text ".Print_Time" at 3848.5,-1064.34 h60
  text "TEXAS INSTRUMENTS" at 5113,-1064.34 h60
M12 Stackup:
  drawing of 191 lines, arcs and shapes, not listed
  text "Layer" at 9790.34,7830 h60
  text "Name" at 10200.26,7830 h60
  text "Material" at 11130,7830 h60
  text "Thickness" at 11989.77,7830 h60
  text "Constant" at 12639.6,7830 h60
  text "Board Layer Stack" at 13209.46,7830 h60
  text "1" at 9790.34,7710 h60
  text "Top Overlay" at 10200.26,7710 h60
  text "2" at 9790.34,7590 h60
  text "Top Solder" at 10200.26,7590 h60
  text "Solder Resist" at 11130,7590 h60
  text "0.40mil" at 11989.77,7590 h60
  text "3.5" at 12639.6,7590 h60
  text "3" at 9790.34,7470 h60
  text "Top Layer" at 10200.26,7470 h60
  text "Copper" at 11130,7470 h60
  text "1.40mil" at 11989.77,7470 h60
  text "4" at 9790.34,7350 h60
  text "Dielectric1" at 10200.26,7350 h60
  text "FR-4" at 11130,7350 h60
  text "59.20mil" at 11989.77,7350 h60
  text "4.8" at 12639.6,7350 h60
  text "5" at 9790.34,7230 h60
  text "Bottom Layer" at 10200.26,7230 h60
  text "Copper" at 11130,7230 h60
  text "1.40mil" at 11989.77,7230 h60
  text "6" at 9790.34,7110 h60
  text "Bottom Solder" at 10200.26,7110 h60
  text "Solder Resist" at 11130,7110 h60
  text "0.40mil" at 11989.77,7110 h60
  text "3.5" at 12639.6,7110 h60
  text "7" at 9790.34,6990 h60
  text "Bottom Overlay" at 10200.26,6990 h60
  text ".Layer_Name" at 577,-858.49 h60
M13 Component Bodies Top:
  text ".Layer_Name" at 577,-858.49 h60
M14 Component Bodies Bottom:
  text ".Layer_Name" at 577,-858.49 h60
M15 Courtyards Top:
  text ".Layer_Name" at 577,-858.49 h60
M16 Courtyards Bottom:
  text ".Layer_Name" at 577,-858.49 h60
Drill Drawing:
  text ".Layer_Name" at 577,-858.49 h60
M17 Embedded Cavity:
  text ".Layer_Name" at 577,-858.49 h60
M18 Embedded Assembly:
  text ".Layer_Name" at 577,-858.49 h60
M19 Embedded Keepout:
  text ".Layer_Name" at 577,-858.49 h60

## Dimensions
79,109.12 to 89,1109.03 on M2 Board Dimensions
102.12,0 to 1102.03,-10 on M2 Board Dimensions
0,-400 to 1000,-400 on M2 Board Dimensions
